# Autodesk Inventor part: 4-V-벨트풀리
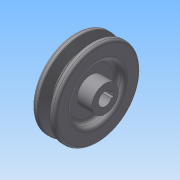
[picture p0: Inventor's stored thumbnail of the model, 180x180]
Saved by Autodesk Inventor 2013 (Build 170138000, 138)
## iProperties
Created: 2015-02
Part Number: 4-V-벨트풀리
Material: 일반
Document SubType Name: Modeling
Designer: Administrator
Density: 1 g/cm^3
Author: Administrator
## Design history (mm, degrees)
sketch "스케치1"
  geometry: L1 (0, 0)-(19, 0); L2 (19, 5.5)-(19, 11); L3 (19, 11)-(13, 11); L4 (13, 11)-(13, 21.5); L5 (13, 21.5)-(19, 21.5); L6 (19, 21.5)-(19, 35.2); L7 (19, 35.2)-(14.325, 35.2); L8 (14.325, 35.2)-(11.574, 26.2); L9 (11.574, 26.2)-(7.426, 26.2); L10 (7.426, 26.2)-(4.675, 35.2); L11 (4.675, 35.2)-(0, 35.2); L12 (0, 35.2)-(0, 21.5); L13 (0, 21.5)-(6, 21.5); L14 (6, 21.5)-(6, 11); L15 (6, 11)-(0, 11); L16 (0, 11)-(0, 5.5); L17 (0, 5.5)-(19, 5.5); 2 further points
  constraints: 34 end point, 7 parallel, 5 horizontal alignment, 4 perpendicular, 4 vertical alignment, 3 collinear, 3 equal length, 2 point on line, 1 horizontal
  dimensions: "d0" = 19 distance of L1.start L1.end; "d1" = 11 diameter of L17 L1; "d2" = 22 diameter of L3 L1; "d3" = 6 distance of L4.end L5.end; "d4" = 43 diameter of L12.end L1; "d5" = 6.3 distance from line of L9 point (13.5, 32.5); "d6" = 2.7 distance from line of point (13.5, 32.5) L7; "d7" = 65 diameter of point (5.5, 32.5) L1; "d8" = 8 distance of point (13.5, 32.5) point (5.5, 32.5); "d9" = 34 deg angle of L8 L10
revolve "회전1" sketch "스케치1" stored, may be unused: angle "d10" = 90 deg
node "작업 평면1"
sketch "스케치3"
  geometry: C1 r 5.5 at (0, 0) reference; C2 r 11 at (0, 0) reference; 1 further point
extrude "돌출1" join sketch "스케치3" stored distance "d12" = 10; taper "d13" = 0 deg
sketch "스케치4"
  geometry: L1 (-2, 7.1)-(2, 7.1); L2 (2, 7.1)-(2, 3.1); L3 (2, 3.1)-(-2, 3.1); L4 (-2, 3.1)-(-2, 7.1); C1 r 5.5 at (0, 0) reference; 1 further point
  constraints: 8 end point, 2 parallel, 1 horizontal, 1 midpoint, 1 perpendicular, 1 vertical alignment
  dimensions: "d14" = 4 distance of L1.start L1.end; "d16" = 12.6 dimension on C1 L1
extrude "돌출2" cut sketch "스케치4" stored distance "d17" = 10; taper "d18" = 0 deg
fillet "모깎기1" dims "d19" = 0.5
fillet "모깎기2" dims "d20" = 2
fillet "모깎기3" dims "d21" = 1
fillet "모깎기4" dims "d22" = 3
node "솔리드1"
node "투영된 루프2"
other parameters: "d11" = 25
